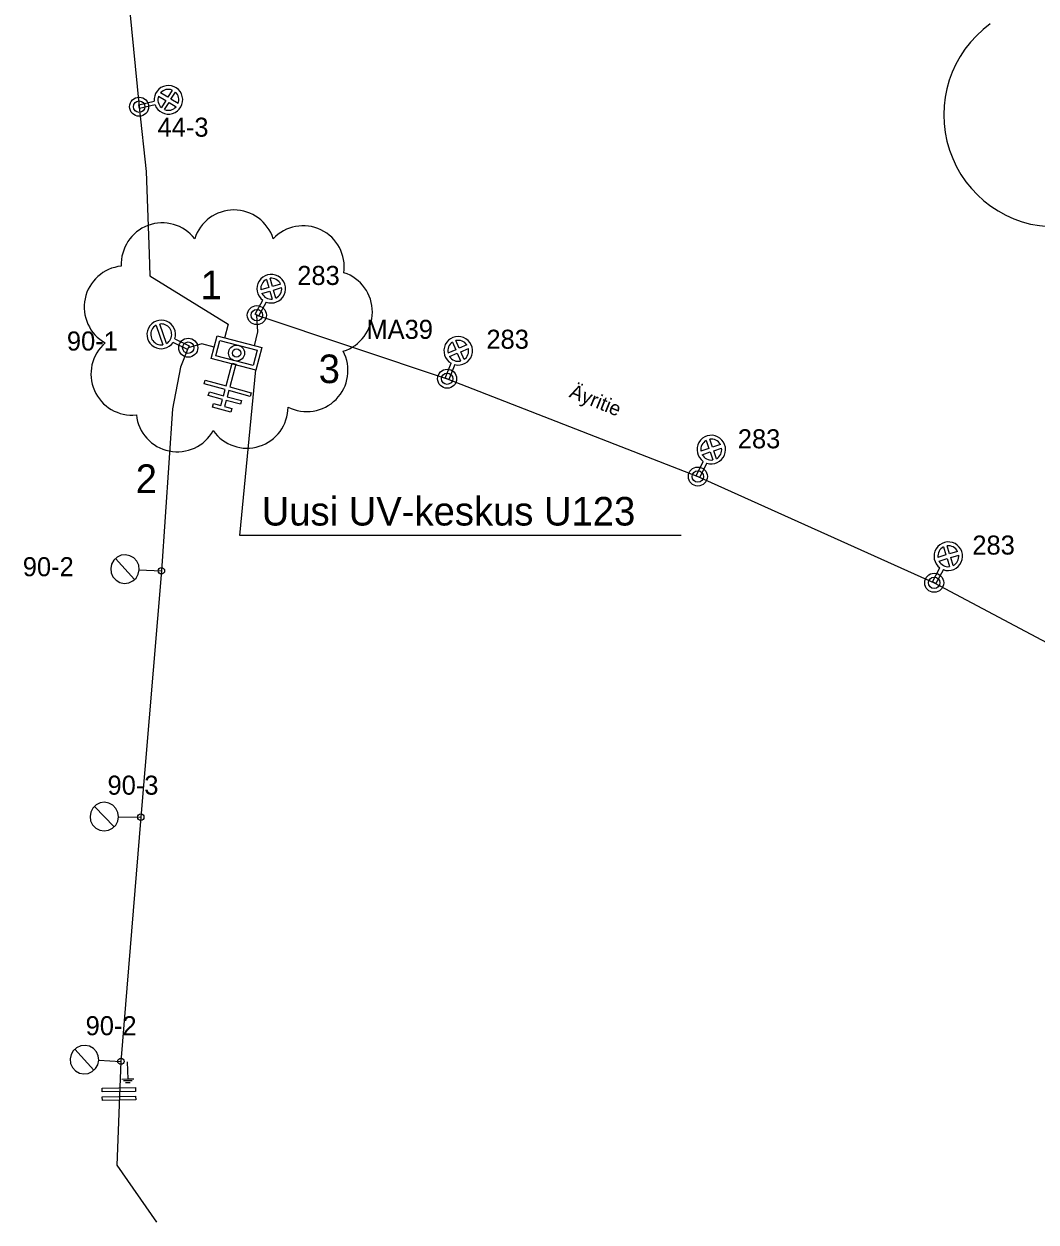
# Model space of a CAD drawing. Extents: x 25497851 to 25498523, y 6686544 to 6687372.
# Drawn here: x 25497924.4 to 25498083.9, y 6686887.2 to 6687075.9 of the extents above; entities that cross this region are included whole.
import ezdxf

# ---------------------------------------------------------------- set-up
doc = ezdxf.new("R2010")
doc.units = 0
for name, color, linetype in [('EL_CABLE_MAA', 7, 'Continuous'), ('KAAPELI', 7, 'Continuous'), ('KESKUS', 7, 'Continuous'), ('KEYGWT_ANNOTATION', 7, 'Continuous'), ('Level 17', 7, 'Continuous'), ('Level 63', 7, 'Continuous'), ('MUU_SUUNNITELMAVIIVA', 7, 'Continuous'), ('MUU_UV-SUUNNITELMASYMBOLI', 7, 'Continuous'), ('PYLVAS', 7, 'Continuous'), ('Taso 1', 7, 'Continuous'), ('TEKSTI_SUUNNITELMA-ALUE', 7, 'Continuous'), ('VALAISIN', 7, 'Continuous'), ('VIITEVIIVA', 7, 'Continuous')]:
    doc.layers.add(name, color=color, linetype=linetype)

msp = doc.modelspace()

# ---------------------------------------------------------------- linework, layer by layer
at = {"layer": 'EL_CABLE_MAA'}
for points in [[(25497946.1, 6686989.76), (25497942.85, 6686950.95)], [(25497942.85, 6686950.95), (25497939.72, 6686912.49)], [(25497939.72, 6686912.49), (25497939.1, 6686896.13), (25497945.31, 6686887.18)]]:
    msp.add_lwpolyline(points, dxfattribs=at)
at = {"layer": 'KAAPELI'}
for p, q in [((25497961.13, 6687030.03), (25497991.11, 6687020.01)), ((25497991.11, 6687020.01), (25498030.62, 6687004.6)), ((25498030.62, 6687004.6), (25498067.85, 6686987.87)), ((25498067.85, 6686987.87), (25498107.28, 6686966.85))]:
    msp.add_line(p, q, dxfattribs=at)
for points in [[(25497943.45, 6687105.13), (25497941.06, 6687078.34), (25497942.59, 6687062.85)], [(25497942.59, 6687062.86), (25497943.72, 6687052.67), (25497944.15, 6687039.66), (25497944.26, 6687036.24), (25497956.6, 6687028.61), (25497956.06, 6687026.41)], [(25497960.75, 6687025.21), (25497961.31, 6687027.41), (25497961.13, 6687030.03)], [(25497950.33, 6687024.9), (25497949.1, 6687021.84), (25497947.87, 6687015.26), (25497946.1, 6686989.76)], [(25497954.41, 6687024.98), (25497952.47, 6687025.48), (25497950.33, 6687024.9)]]:
    msp.add_lwpolyline(points, dxfattribs=at)
at = {"layer": 'KESKUS'}
for p, q in [((25497953.94, 6687023.19), (25497954.87, 6687026.77)), ((25497954.67, 6687023.62), (25497955.3, 6687026.03)), ((25497954.87, 6687026.77), (25497961.94, 6687024.92)), ((25497955.3, 6687026.03), (25497961.2, 6687024.49)), ((25497961.2, 6687024.49), (25497960.57, 6687022.07)), ((25497961.94, 6687024.92), (25497961, 6687021.34)), ((25497961, 6687021.34), (25497953.94, 6687023.19)), ((25497960.57, 6687022.07), (25497954.67, 6687023.62))]:
    msp.add_line(p, q, dxfattribs=at)
for radius in [1.25, 0.65]:
    msp.add_circle((25497957.94, 6687024.05), radius, dxfattribs=at)
at = {"layer": 'Level 17'}
for points in [[(25497940.73, 6686912.4), (25497940.82, 6686909.68)], [(25497940.83, 6686909.67), (25497939.88, 6686909.64)], [(25497940.82, 6686909.42), (25497940.15, 6686909.4)], [(25497940.46, 6686909.14), (25497940.83, 6686909.15)], [(25497941.49, 6686909.44), (25497940.82, 6686909.42)], [(25497941.77, 6686909.7), (25497940.83, 6686909.67)], [(25497940.83, 6686909.15), (25497941.2, 6686909.17)]]:
    msp.add_lwpolyline(points, dxfattribs=at)
at = {"layer": 'MUU_SUUNNITELMAVIIVA'}
for centre, radius, start, end in [((25498087.01, 6687061.58), 17.65, 125.8219, 270.8219), ((25497957.53, 6687040.11), 6.48, 17.5, 162.5), ((25497946.25, 6687038.08), 6.48, 37.9458, 182.9458), ((25497968.43, 6687037.63), 6.47, 351.809, 136.809), ((25497940.42, 6687031.29), 6.48, 95.655, 240.655), ((25497972.85, 6687030.54), 6.48, 287.0438, 72.0438), ((25497941.48, 6687020.75), 6.48, 130.9089, 275.9089), ((25497969.01, 6687021.32), 6.48, 242.8204, 27.8204), ((25497959.57, 6687015.55), 6.48, 214.9926, 359.9926), ((25497948.6, 6687014.98), 6.48, 185.996, 330.996)]:
    msp.add_arc(centre, radius, start, end, dxfattribs=at)
at = {"layer": 'MUU_UV-SUUNNITELMASYMBOLI'}
for p, q in [((25497956.31, 6687018.87), (25497957.27, 6687022.44)), ((25497957.85, 6687022.28), (25497956.89, 6687018.71)), ((25497957.27, 6687022.44), (25497957.85, 6687022.28)), ((25497952.82, 6687019.19), (25497952.98, 6687019.77)), ((25497956.15, 6687018.29), (25497952.82, 6687019.19)), ((25497952.98, 6687019.77), (25497956.31, 6687018.87)), ((25497955.89, 6687017.32), (25497956.15, 6687018.29)), ((25497956.73, 6687018.13), (25497956.47, 6687017.17)), ((25497960.06, 6687017.23), (25497956.73, 6687018.13)), ((25497956.89, 6687018.71), (25497960.22, 6687017.81)), ((25497953.49, 6687017.35), (25497953.65, 6687017.93)), ((25497955.73, 6687016.74), (25497953.49, 6687017.35)), ((25497953.65, 6687017.93), (25497955.89, 6687017.32)), ((25497955.47, 6687015.78), (25497955.73, 6687016.74)), ((25497956.31, 6687016.59), (25497956.05, 6687015.62)), ((25497958.56, 6687015.98), (25497956.31, 6687016.59)), ((25497956.47, 6687017.17), (25497958.71, 6687016.56)), ((25497958.71, 6687016.56), (25497958.56, 6687015.98)), ((25497960.22, 6687017.81), (25497960.06, 6687017.23)), ((25497954.16, 6687015.51), (25497954.32, 6687016.09)), ((25497957.06, 6687014.73), (25497954.16, 6687015.51)), ((25497954.32, 6687016.09), (25497955.47, 6687015.78)), ((25497956.05, 6687015.62), (25497957.21, 6687015.31)), ((25497957.21, 6687015.31), (25497957.06, 6687014.73)), ((25497936.77, 6686908.27), (25497942.02, 6686908.36)), ((25497936.78, 6686907.67), (25497936.77, 6686908.27)), ((25497942.03, 6686907.76), (25497936.78, 6686907.67)), ((25497936.79, 6686906.91), (25497942.04, 6686907)), ((25497936.8, 6686906.31), (25497936.79, 6686906.91)), ((25497942.02, 6686908.36), (25497942.03, 6686907.76)), ((25497942.04, 6686907), (25497942.05, 6686906.4)), ((25497942.05, 6686906.4), (25497936.8, 6686906.31))]:
    msp.add_line(p, q, dxfattribs=at)
at = {"layer": 'PYLVAS'}
for centre, radius in [((25497942.59, 6687062.86), 1.5), ((25497942.59, 6687062.86), 0.9), ((25497961.13, 6687030.03), 1.5), ((25497961.13, 6687030.03), 0.9), ((25497950.33, 6687024.9), 1.5), ((25497950.33, 6687024.9), 0.9), ((25497991.11, 6687020.01), 1.5), ((25497991.11, 6687020.01), 0.9), ((25498030.62, 6687004.6), 1.5), ((25498030.62, 6687004.6), 0.9), ((25498067.85, 6686987.87), 1.5), ((25498067.85, 6686987.87), 0.9)]:
    msp.add_circle(centre, radius, dxfattribs=at)
at = {"layer": 'Taso 1'}
for p, q in [((25497938.86, 6686991.67), (25497941.85, 6686988.39)), ((25497942.6, 6686989.92), (25497946.1, 6686989.76)), ((25497935.56, 6686952.63), (25497938.65, 6686949.44)), ((25497939.35, 6686951), (25497942.85, 6686950.95)), ((25497932.48, 6686914.4), (25497935.47, 6686911.11)), ((25497936.22, 6686912.65), (25497939.72, 6686912.49))]:
    msp.add_line(p, q, dxfattribs=at)
for points in [[(25497938.11, 6686990.14), (25497938.19, 6686989.44), (25497938.47, 6686988.79), (25497938.95, 6686988.27), (25497939.56, 6686987.92), (25497940.25, 6686987.78), (25497940.95, 6686987.86), (25497941.59, 6686988.15), (25497942.11, 6686988.62), (25497942.46, 6686989.23), (25497942.6, 6686989.92), (25497942.52, 6686990.62), (25497942.23, 6686991.27), (25497941.76, 6686991.79), (25497941.15, 6686992.13), (25497940.46, 6686992.28), (25497939.76, 6686992.2), (25497939.12, 6686991.91), (25497938.6, 6686991.44), (25497938.25, 6686990.82)], [(25497934.86, 6686951.07), (25497934.95, 6686950.37), (25497935.26, 6686949.74), (25497935.75, 6686949.24), (25497936.38, 6686948.91), (25497937.07, 6686948.79), (25497937.77, 6686948.89), (25497938.4, 6686949.2), (25497938.9, 6686949.69), (25497939.23, 6686950.31), (25497939.35, 6686951), (25497939.25, 6686951.7), (25497938.94, 6686952.33), (25497938.45, 6686952.84), (25497937.83, 6686953.16), (25497937.14, 6686953.29), (25497936.44, 6686953.19), (25497935.81, 6686952.88), (25497935.31, 6686952.39), (25497934.98, 6686951.76)], [(25497931.73, 6686912.86), (25497931.8, 6686912.16), (25497932.09, 6686911.52), (25497932.57, 6686911), (25497933.18, 6686910.65), (25497933.87, 6686910.51), (25497934.57, 6686910.59), (25497935.21, 6686910.88), (25497935.73, 6686911.35), (25497936.08, 6686911.96), (25497936.22, 6686912.65), (25497936.14, 6686913.35), (25497935.85, 6686913.99), (25497935.38, 6686914.51), (25497934.77, 6686914.86), (25497934.08, 6686915), (25497933.38, 6686914.93), (25497932.74, 6686914.64), (25497932.22, 6686914.16), (25497931.87, 6686913.55)]]:
    msp.add_lwpolyline(points, close=True, dxfattribs=at)
for centre in [(25497946.1, 6686989.76), (25497942.85, 6686950.95), (25497939.72, 6686912.49)]:
    msp.add_circle(centre, 0.5, dxfattribs=at)
at = {"layer": 'VALAISIN'}
for p, q in [((25497947.8, 6687065.48), (25497947.1, 6687064.36)), ((25497942.52, 6687063.15), (25497944.96, 6687063.72)), ((25497945.66, 6687064.54), (25497946.79, 6687063.84)), ((25497947.1, 6687064.36), (25497945.98, 6687065.05)), ((25497946.79, 6687063.84), (25497946.09, 6687062.72)), ((25497946.6, 6687062.4), (25497947.3, 6687063.53)), ((25497947.3, 6687063.53), (25497948.42, 6687062.83)), ((25497947.61, 6687064.04), (25497948.31, 6687065.16)), ((25497948.74, 6687063.34), (25497947.61, 6687064.04)), ((25497942.66, 6687062.56), (25497942.52, 6687063.15)), ((25497945.1, 6687063.14), (25497942.66, 6687062.56)), ((25497962.66, 6687035.66), (25497963.03, 6687034.39)), ((25497963.61, 6687034.56), (25497963.23, 6687035.83)), ((25497963.03, 6687034.39), (25497961.76, 6687034.02)), ((25497961.93, 6687033.44), (25497963.2, 6687033.82)), ((25497963.2, 6687033.82), (25497963.57, 6687032.55)), ((25497964.88, 6687034.93), (25497963.61, 6687034.56)), ((25497963.78, 6687033.98), (25497965.04, 6687034.36)), ((25497964.15, 6687032.71), (25497963.78, 6687033.98)), ((25497960.87, 6687030.17), (25497962.07, 6687032.37)), ((25497962.6, 6687032.09), (25497961.39, 6687029.88)), ((25497961.39, 6687029.88), (25497960.87, 6687030.17)), ((25497945.27, 6687028.42), (25497946.31, 6687025.35)), ((25497946.88, 6687025.55), (25497945.83, 6687028.62)), ((25497950.2, 6687024.63), (25497947.94, 6687025.73)), ((25497948.21, 6687026.27), (25497950.46, 6687025.17)), ((25497991.94, 6687025.78), (25497992.46, 6687024.57)), ((25497993.01, 6687024.81), (25497992.49, 6687026.02)), ((25497950.46, 6687025.17), (25497950.2, 6687024.63)), ((25497992.46, 6687024.57), (25497991.25, 6687024.04)), ((25497991.49, 6687023.49), (25497992.7, 6687024.02)), ((25497992.7, 6687024.02), (25497993.23, 6687022.81)), ((25497994.23, 6687025.33), (25497993.01, 6687024.81)), ((25497993.25, 6687024.26), (25497994.46, 6687024.78)), ((25497993.78, 6687023.04), (25497993.25, 6687024.26)), ((25497990.83, 6687020.12), (25497991.76, 6687022.45)), ((25497992.31, 6687022.23), (25497991.39, 6687019.9)), ((25497991.39, 6687019.9), (25497990.83, 6687020.12)), ((25498032.35, 6687009.04), (25498031.09, 6687008.61)), ((25498031.92, 6687010.29), (25498032.35, 6687009.04)), ((25498032.91, 6687009.23), (25498032.49, 6687010.48)), ((25498034.17, 6687009.65), (25498032.91, 6687009.23)), ((25498033.11, 6687008.66), (25498034.36, 6687009.08)), ((25498030.36, 6687004.73), (25498031.47, 6687006.98)), ((25498031.29, 6687008.04), (25498032.54, 6687008.47)), ((25498032.54, 6687008.47), (25498032.96, 6687007.21)), ((25498033.53, 6687007.41), (25498033.11, 6687008.66)), ((25498032.01, 6687006.72), (25498030.89, 6687004.47)), ((25498030.89, 6687004.47), (25498030.36, 6687004.73)), ((25498070.27, 6686992.43), (25498069.89, 6686993.69)), ((25498069.7, 6686992.25), (25498068.44, 6686991.87)), ((25498069.32, 6686993.52), (25498069.7, 6686992.25)), ((25498071.54, 6686992.81), (25498070.27, 6686992.43)), ((25498070.45, 6686991.85), (25498071.71, 6686992.24)), ((25498070.83, 6686990.59), (25498070.45, 6686991.85)), ((25498067.58, 6686988.01), (25498068.76, 6686990.23)), ((25498069.29, 6686989.95), (25498068.11, 6686987.73)), ((25498068.61, 6686991.29), (25498069.88, 6686991.68)), ((25498069.88, 6686991.68), (25498070.26, 6686990.41)), ((25498068.11, 6686987.73), (25498067.58, 6686988.01))]:
    msp.add_line(p, q, dxfattribs=at)
for centre, radius, start, end in [((25497947.2, 6687063.94), 2.25, 13.2418, 185.5795), ((25497947.2, 6687063.94), 1.65, 68.7175, 137.7661), ((25497947.2, 6687063.94), 2.25, 200.904, 13.2418), ((25497947.2, 6687063.94), 1.65, 158.7175, 193.2418), ((25497947.2, 6687063.94), 1.65, 193.2418, 227.7661), ((25497947.2, 6687063.94), 1.65, 13.2418, 47.7661), ((25497947.2, 6687063.94), 1.65, 338.7175, 13.2418), ((25497947.2, 6687063.94), 1.65, 248.7175, 317.7661), ((25497963.4, 6687034.19), 2.25, 61.3434, 233.6812), ((25497963.4, 6687034.19), 1.65, 116.8191, 185.8678), ((25497963.4, 6687034.19), 2.25, 249.0057, 61.3434), ((25497963.4, 6687034.19), 1.65, 61.3434, 95.8678), ((25497963.4, 6687034.19), 1.65, 26.8191, 61.3434), ((25497963.4, 6687034.19), 1.65, 206.8191, 241.3434), ((25497963.4, 6687034.19), 1.65, 296.8191, 5.8678), ((25497963.4, 6687034.19), 1.65, 241.3434, 275.8678), ((25497946.07, 6687026.99), 2.25, 153.8595, 326.1972), ((25497946.07, 6687026.99), 2.25, 341.5217, 153.8595), ((25497946.07, 6687026.99), 1.65, 153.8595, 278.3838), ((25497946.07, 6687026.99), 1.65, 119.3352, 153.8595), ((25497946.07, 6687026.99), 1.65, 333.8595, 98.3838), ((25497946.07, 6687026.99), 1.65, 299.3352, 333.8595), ((25497992.86, 6687024.41), 2.25, 68.4031, 240.7408), ((25497992.86, 6687024.41), 1.65, 123.8788, 192.9274), ((25497992.86, 6687024.41), 2.25, 256.0653, 68.4031), ((25497992.86, 6687024.41), 1.65, 68.4031, 102.9274), ((25497992.86, 6687024.41), 1.65, 33.8788, 68.4031), ((25497992.86, 6687024.41), 1.65, 303.8788, 12.9274), ((25497992.86, 6687024.41), 1.65, 213.8788, 248.4031), ((25497992.86, 6687024.41), 1.65, 248.4031, 282.9274), ((25498032.73, 6687008.85), 2.25, 63.6694, 236.0071), ((25498032.73, 6687008.85), 2.25, 251.3316, 63.6694), ((25498032.73, 6687008.85), 1.65, 119.145, 188.1937), ((25498032.73, 6687008.85), 1.65, 63.6694, 98.1937), ((25498032.73, 6687008.85), 1.65, 29.145, 63.6694), ((25498032.73, 6687008.85), 1.65, 299.145, 8.1937), ((25498032.73, 6687008.85), 1.65, 209.145, 243.6694), ((25498032.73, 6687008.85), 1.65, 243.6694, 278.1937), ((25498070.07, 6686992.05), 2.25, 61.9449, 234.2826), ((25498070.07, 6686992.05), 2.25, 249.6071, 61.9449), ((25498070.07, 6686992.05), 1.65, 61.9449, 96.4692), ((25498070.07, 6686992.05), 1.65, 117.4206, 186.4692), ((25498070.07, 6686992.05), 1.65, 297.4206, 6.4692), ((25498070.07, 6686992.05), 1.65, 27.4206, 61.9449), ((25498070.07, 6686992.05), 1.65, 207.4206, 241.9449), ((25498070.07, 6686992.05), 1.65, 241.9449, 276.4692)]:
    msp.add_arc(centre, radius, start, end, dxfattribs=at)
at = {"layer": 'VIITEVIIVA'}
msp.add_lwpolyline([(25498027.98, 6686995.29), (25497958.46, 6686995.29), (25497960.95, 6687021.39)], dxfattribs=at)

# ---------------------------------------------------------------- texts
at = {"layer": 'KEYGWT_ANNOTATION'}
for s, p in [('44-3', (25497945.49, 6687058.13)), ('283', (25497967.5, 6687034.78)), ('MA39', (25497978.4, 6687026.29)), ('283', (25497997.3, 6687024.73)), ('90-1', (25497931.21, 6687024.45)), ('283', (25498036.91, 6687009.05)), ('283', (25498073.86, 6686992.31)), ('90-2', (25497924.26, 6686988.9)), ('90-3', (25497937.61, 6686954.49)), ('90-2', (25497934.16, 6686916.6))]:
    msp.add_text(s, height=3, dxfattribs=at).set_placement(p)
at = {"layer": 'Level 63'}
msp.add_text('(C) KEYPRO 2000', height=0.0001, rotation=1.8, dxfattribs=at).set_placement((25497940.46, 6686909.14))
at = {"layer": 'TEKSTI_SUUNNITELMA-ALUE'}
for s, p in [('1', (25497952.27, 6687032.53)), ('3', (25497970.88, 6687019.32)), ('2', (25497942.05, 6687002.02)), ('Uusi UV-keskus U123', (25497961.9, 6686996.89))]:
    msp.add_text(s, height=4.5, dxfattribs=at).set_placement(p)
msp.add_text('Äyritie', height=2.25, rotation=337.8755, dxfattribs=at).set_placement((25498010.2, 6687017.17))

doc.saveas('drawing.dxf')
